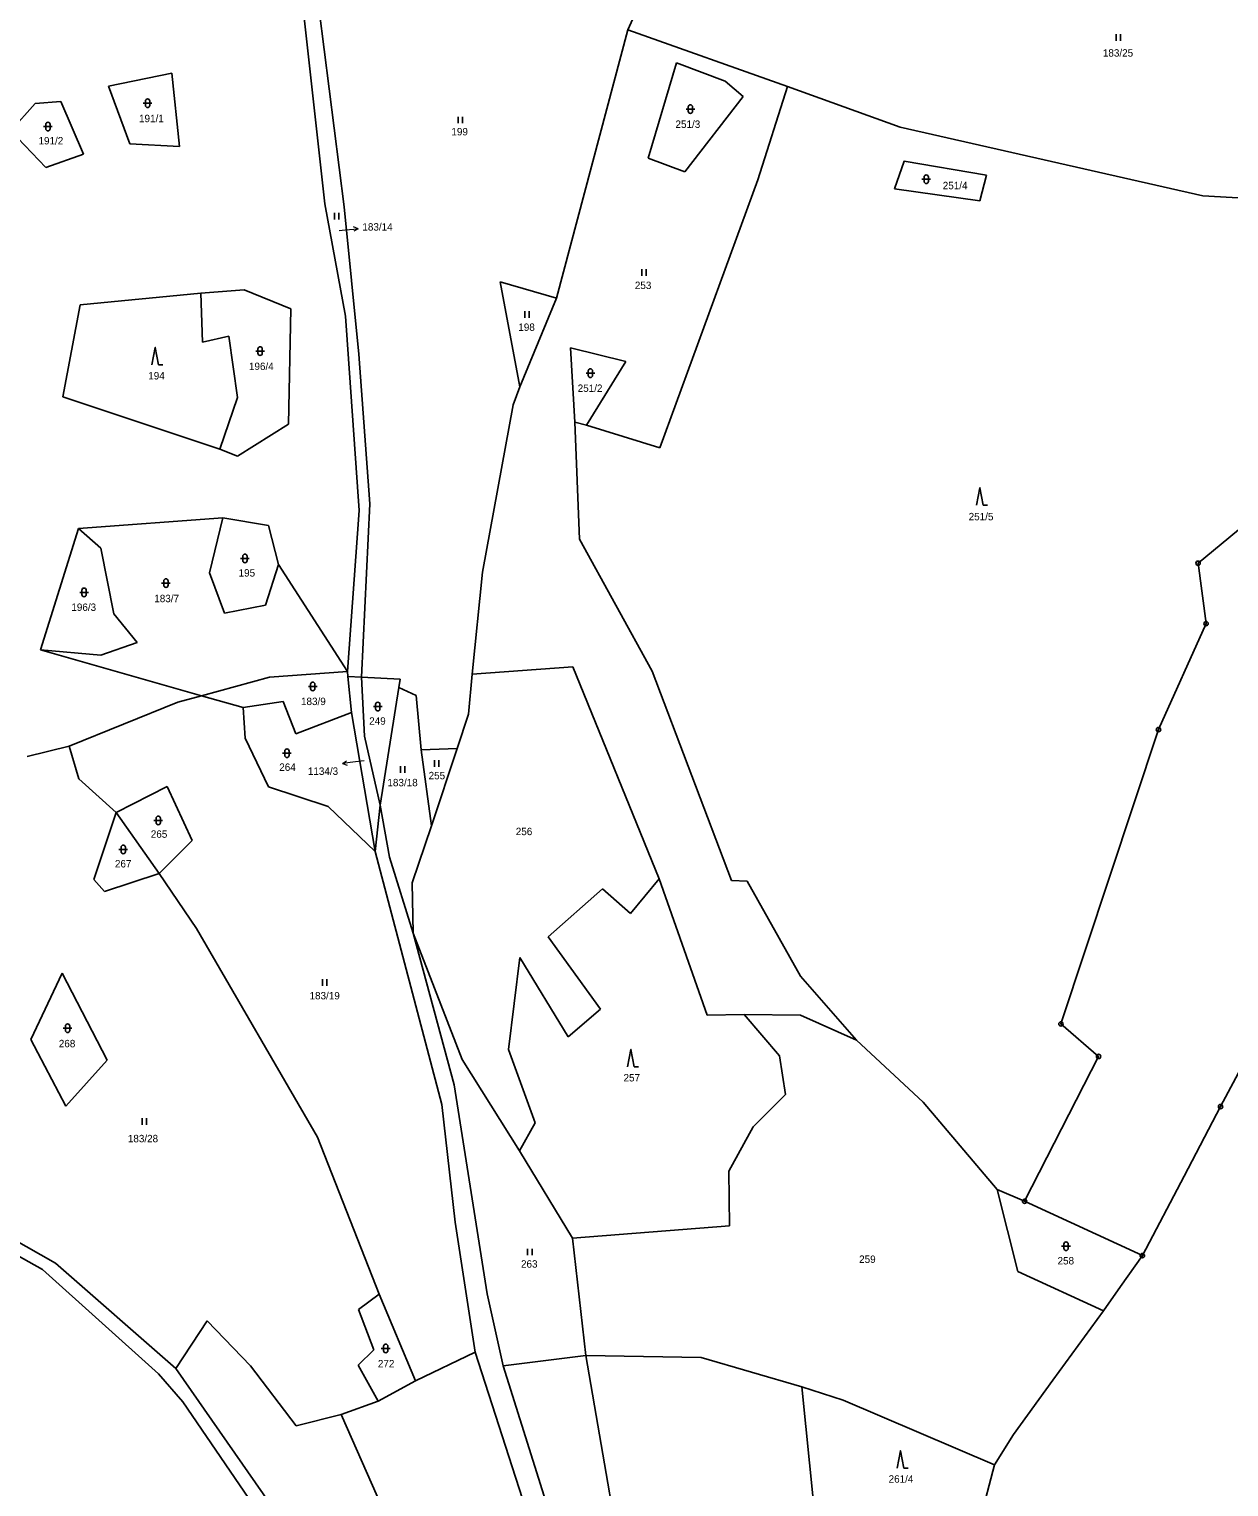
# Model space of a CAD drawing. Extents: x -765428 to -762163, y -1107632 to -1104975.
# Drawn here: x -763021.2 to -762745.6, y -1106469 to -1106134.4 of the extents above; entities that cross this region are included whole.
import ezdxf
from ezdxf.enums import TextEntityAlignment as Align

# ---------------------------------------------------------------- set-up
doc = ezdxf.new("R2010")
doc.units = 0
doc.header["$LTSCALE"] = 0.68
for name, color, linetype, lineweight in [('1', 7, 'Continuous', 25), ('3', 7, 'Continuous', 25), ('7', 7, 'Continuous', 13), ('8', 7, 'Continuous', 25)]:
    doc.layers.add(name, color=color, linetype=linetype, lineweight=lineweight)
doc.layers.add('2', color=7, linetype='Continuous')

msp = doc.modelspace()

# ---------------------------------------------------------------- linework, layer by layer
at = {"layer": '1'}
for p, q in [((-762874.94, -1106114.98), (-762883.63, -1106134.57)), ((-762953.22, -1106174.49), (-762958.16, -1106130.43)), ((-762954.53, -1106130.03), (-762948.82, -1106175.16)), ((-762883.63, -1106134.57), (-762900.02, -1106196.11)), ((-762883.63, -1106134.57), (-762847.02, -1106147.59)), ((-762872.47, -1106142.09), (-762879.01, -1106164.03)), ((-762861.28, -1106146.3), (-762872.47, -1106142.09)), ((-763002.95, -1106147.5), (-762988.37, -1106144.49)), ((-762988.37, -1106144.49), (-762986.6, -1106161.29)), ((-762857.19, -1106149.85), (-762861.28, -1106146.3)), ((-763002.95, -1106147.5), (-762998.05, -1106160.73)), ((-762847.02, -1106147.59), (-762853.81, -1106169.01)), ((-762821.13, -1106156.89), (-762847.02, -1106147.59)), ((-763019.8, -1106151.45), (-763025.33, -1106157.75)), ((-763019.8, -1106151.45), (-763013.86, -1106150.98)), ((-763013.86, -1106150.98), (-763008.65, -1106163.09)), ((-762870.58, -1106167.18), (-762857.19, -1106149.85)), ((-763025.33, -1106157.75), (-763017.35, -1106166.16)), ((-762751.57, -1106172.68), (-762821.13, -1106156.89)), ((-763017.35, -1106166.16), (-763008.65, -1106163.09)), ((-762986.6, -1106161.29), (-762998.05, -1106160.73)), ((-762879.01, -1106164.03), (-762870.58, -1106167.18)), ((-762853.81, -1106169.01), (-762876.27, -1106230.52)), ((-762802.79, -1106173.83), (-762801.25, -1106167.93)), ((-762822.38, -1106171.04), (-762802.79, -1106173.83)), ((-762723.14, -1106174.24), (-762751.57, -1106172.68)), ((-762948.51, -1106200.27), (-762953.22, -1106174.49)), ((-762948.82, -1106175.16), (-762945.42, -1106209.03)), ((-762908.47, -1106216.48), (-762912.96, -1106192.37)), ((-762912.96, -1106192.37), (-762900.02, -1106196.11)), ((-763009.43, -1106197.65), (-762981.74, -1106195.01)), ((-762981.74, -1106195.01), (-762971.77, -1106194.24)), ((-762981.74, -1106195.01), (-762981.36, -1106206.21)), ((-762971.77, -1106194.24), (-762961.03, -1106198.6)), ((-762900.02, -1106196.11), (-762908.47, -1106216.48)), ((-763009.43, -1106197.65), (-763013.42, -1106218.83)), ((-762961.03, -1106198.6), (-762961.58, -1106225.06)), ((-762945.33, -1106244.86), (-762948.51, -1106200.27)), ((-762981.36, -1106206.21), (-762975.31, -1106204.86)), ((-762975.31, -1106204.86), (-762973.31, -1106218.96)), ((-762945.42, -1106209.03), (-762942.88, -1106243.36)), ((-762895.84, -1106224.64), (-762896.83, -1106207.57)), ((-762896.83, -1106207.57), (-762884.12, -1106210.68)), ((-762884.12, -1106210.68), (-762893.17, -1106225.31)), ((-762908.47, -1106216.48), (-762909.99, -1106220.62)), ((-762699.78, -1106213.38), (-762752.7, -1106256.98)), ((-763013.42, -1106218.83), (-762977.37, -1106230.81)), ((-762973.31, -1106218.96), (-762977.37, -1106230.81)), ((-762909.99, -1106220.62), (-762917.04, -1106259.06)), ((-762961.58, -1106225.06), (-762973.27, -1106232.38)), ((-762893.17, -1106225.31), (-762895.84, -1106224.64)), ((-762895.84, -1106224.64), (-762894.75, -1106251.44)), ((-762876.27, -1106230.52), (-762893.17, -1106225.31)), ((-762973.27, -1106232.38), (-762977.37, -1106230.81)), ((-762942.88, -1106243.36), (-762944.85, -1106283.11)), ((-763009.82, -1106249.02), (-762976.69, -1106246.6)), ((-762976.69, -1106246.6), (-762979.73, -1106259.18)), ((-762976.69, -1106246.6), (-762966.19, -1106248.32)), ((-762945.33, -1106244.86), (-762948.06, -1106281.83)), ((-763018.57, -1106276.87), (-763009.82, -1106249.02)), ((-763009.82, -1106249.02), (-763004.68, -1106253.55)), ((-762966.19, -1106248.32), (-762963.92, -1106257.26)), ((-762894.75, -1106251.44), (-762878.05, -1106281.74)), ((-763004.68, -1106253.55), (-763001.73, -1106268.63)), ((-762976.25, -1106268.47), (-762979.73, -1106259.18)), ((-762963.92, -1106257.26), (-762966.86, -1106266.59)), ((-762948.06, -1106281.83), (-762963.92, -1106257.26)), ((-762917.04, -1106259.06), (-762919.4, -1106282.45)), ((-762752.7, -1106256.98), (-762750.86, -1106270.85)), ((-762966.86, -1106266.59), (-762976.25, -1106268.47)), ((-763001.73, -1106268.63), (-762996.33, -1106275.2)), ((-762750.86, -1106270.85), (-762761.78, -1106295.18)), ((-763018.57, -1106276.87), (-762981.56, -1106287.41)), ((-763004.69, -1106278.08), (-763018.57, -1106276.87)), ((-762996.33, -1106275.2), (-763004.69, -1106278.08)), ((-762965.93, -1106283.17), (-762981.56, -1106287.41)), ((-762948.06, -1106281.83), (-762965.93, -1106283.17)), ((-762947.94, -1106282.96), (-762948.06, -1106281.83)), ((-762947.09, -1106291.24), (-762947.94, -1106282.96)), ((-762944.85, -1106283.11), (-762947.94, -1106282.96)), ((-762944.85, -1106283.11), (-762935.91, -1106283.6)), ((-762944.17, -1106296.72), (-762944.85, -1106283.11)), ((-762935.91, -1106283.6), (-762936.22, -1106285.53)), ((-762919.4, -1106282.45), (-762920.27, -1106291.64)), ((-762896.27, -1106280.77), (-762919.4, -1106282.45)), ((-762876.47, -1106329.44), (-762896.27, -1106280.77)), ((-762878.05, -1106281.74), (-762859.84, -1106329.79)), ((-762936.22, -1106285.53), (-762940.52, -1106312.56)), ((-762932.27, -1106287.34), (-762936.22, -1106285.53)), ((-762986.97, -1106288.88), (-763011.94, -1106299.02)), ((-762981.56, -1106287.41), (-762986.97, -1106288.88)), ((-762981.56, -1106287.41), (-762972.02, -1106290.13)), ((-762972.02, -1106290.13), (-762962.81, -1106288.74)), ((-762971.56, -1106297.12), (-762972.02, -1106290.13)), ((-762962.81, -1106288.74), (-762959.91, -1106296.19)), ((-762931.15, -1106299.82), (-762932.27, -1106287.34)), ((-762959.91, -1106296.19), (-762947.09, -1106291.24)), ((-762947.09, -1106291.24), (-762941.72, -1106323.15)), ((-762920.27, -1106291.64), (-762922.88, -1106299.54)), ((-762940.52, -1106312.56), (-762944.17, -1106296.72)), ((-762761.78, -1106295.18), (-762784.18, -1106362.74)), ((-763021.57, -1106301.33), (-763011.94, -1106299.02)), ((-763011.94, -1106299.02), (-763009.74, -1106306.46)), ((-762966.18, -1106308.31), (-762971.56, -1106297.12)), ((-762931.15, -1106299.82), (-762922.88, -1106299.54)), ((-762928.73, -1106317.26), (-762931.15, -1106299.82)), ((-762922.88, -1106299.54), (-762928.73, -1106317.26)), ((-763009.74, -1106306.46), (-763001.15, -1106314.19)), ((-763001.15, -1106314.19), (-762989.48, -1106308.21)), ((-762989.48, -1106308.21), (-762983.75, -1106320.67)), ((-762952.46, -1106312.86), (-762966.18, -1106308.31)), ((-762941.72, -1106323.15), (-762952.46, -1106312.86)), ((-762941.72, -1106323.15), (-762940.52, -1106312.56)), ((-762940.52, -1106312.56), (-762938.4, -1106324.46)), ((-763001.15, -1106314.19), (-763006.26, -1106329.57)), ((-763001.15, -1106314.19), (-762991.29, -1106328.18)), ((-762928.73, -1106317.26), (-762933.18, -1106330.37)), ((-762991.29, -1106328.18), (-762983.75, -1106320.67)), ((-762941.72, -1106323.15), (-762926.38, -1106381.22)), ((-762938.4, -1106324.46), (-762932.94, -1106341.9)), ((-763003.81, -1106332.37), (-763006.26, -1106329.57)), ((-762991.29, -1106328.18), (-763003.81, -1106332.37)), ((-762982.74, -1106340.81), (-762991.29, -1106328.18)), ((-762933.18, -1106330.37), (-762932.94, -1106341.9)), ((-762883.03, -1106337.38), (-762876.47, -1106329.44)), ((-762865.46, -1106360.74), (-762876.47, -1106329.44)), ((-762859.84, -1106329.79), (-762856.21, -1106329.95)), ((-762856.21, -1106329.95), (-762844.02, -1106351.77)), ((-762901.92, -1106342.78), (-762889.48, -1106331.73)), ((-762889.48, -1106331.73), (-762883.03, -1106337.38)), ((-762954.96, -1106388.71), (-762982.74, -1106340.81)), ((-762932.94, -1106341.9), (-762921.73, -1106370.95)), ((-762932.94, -1106341.9), (-762923.54, -1106376.71)), ((-762889.91, -1106359.38), (-762901.92, -1106342.78)), ((-762911.04, -1106368.65), (-762908.47, -1106347.47)), ((-762908.47, -1106347.47), (-762897.32, -1106365.68)), ((-762747.53, -1106381.72), (-762729.6, -1106347.98)), ((-763020.74, -1106366.32), (-763013.55, -1106351.06)), ((-763013.55, -1106351.06), (-763003.25, -1106371.1)), ((-762844.02, -1106351.77), (-762831.17, -1106366.51)), ((-762897.32, -1106365.68), (-762889.91, -1106359.38)), ((-762856.93, -1106360.55), (-762865.46, -1106360.74)), ((-762848.84, -1106370.1), (-762856.93, -1106360.55)), ((-762844.02, -1106360.74), (-762856.93, -1106360.55)), ((-762831.17, -1106366.51), (-762844.02, -1106360.74)), ((-762784.18, -1106362.74), (-762775.53, -1106370.22)), ((-763012.76, -1106381.62), (-763020.74, -1106366.32)), ((-762831.17, -1106366.51), (-762815.82, -1106380.71)), ((-762904.96, -1106385.42), (-762911.04, -1106368.65)), ((-762847.43, -1106378.98), (-762848.84, -1106370.1)), ((-762775.53, -1106370.22), (-762792.54, -1106403.46)), ((-763003.25, -1106371.1), (-763012.76, -1106381.62)), ((-762921.73, -1106370.95), (-762908.57, -1106391.9)), ((-762923.54, -1106376.71), (-762915.96, -1106424.68)), ((-762854.86, -1106386.36), (-762847.43, -1106378.98)), ((-762926.38, -1106381.22), (-762923.34, -1106408.29)), ((-762815.82, -1106380.71), (-762798.86, -1106400.73)), ((-762755.92, -1106397.69), (-762747.53, -1106381.72)), ((-762908.57, -1106391.9), (-762904.96, -1106385.42)), ((-762860.49, -1106396.51), (-762854.86, -1106386.36)), ((-762940.76, -1106424.75), (-762954.96, -1106388.71)), ((-762908.57, -1106391.9), (-762896.34, -1106411.96)), ((-763015.12, -1106417.7), (-763052.02, -1106396.62)), ((-762860.28, -1106409.12), (-762860.49, -1106396.51)), ((-762798.86, -1106400.73), (-762794.11, -1106419.56)), ((-762798.86, -1106400.73), (-762792.54, -1106403.46)), ((-762765.49, -1106415.92), (-762755.92, -1106397.69)), ((-762792.54, -1106403.46), (-762765.49, -1106415.92)), ((-762923.34, -1106408.29), (-762918.73, -1106438.09)), ((-762896.34, -1106411.96), (-762860.28, -1106409.12)), ((-762896.34, -1106411.96), (-762893.32, -1106438.88)), ((-762770.5, -1106423.04), (-762765.49, -1106415.92)), ((-762991.47, -1106443.04), (-763018.11, -1106419.15)), ((-762987.49, -1106441.88), (-763015.12, -1106417.7)), ((-762794.11, -1106419.56), (-762774.42, -1106428.6)), ((-762774.42, -1106428.6), (-762770.5, -1106423.04)), ((-762945.53, -1106428.28), (-762940.76, -1106424.75)), ((-762940.76, -1106424.75), (-762932.41, -1106444.7)), ((-762915.96, -1106424.68), (-762912.26, -1106441.21)), ((-762942, -1106437.59), (-762945.53, -1106428.28)), ((-762786.01, -1106444.52), (-762774.42, -1106428.6)), ((-762980.28, -1106430.9), (-762987.49, -1106441.88)), ((-762970.31, -1106441.23), (-762980.28, -1106430.9)), ((-762945.56, -1106441.12), (-762942, -1106437.59)), ((-762918.73, -1106438.09), (-762932.41, -1106444.7)), ((-762901.42, -1106491.68), (-762918.73, -1106438.09)), ((-762893.32, -1106438.88), (-762866.78, -1106439.33)), ((-762866.78, -1106439.33), (-762843.73, -1106446.08)), ((-762985.88, -1106449.49), (-762991.47, -1106443.04)), ((-762965.65, -1106473.11), (-762987.49, -1106441.88)), ((-762959.79, -1106454.99), (-762970.31, -1106441.23)), ((-762941.01, -1106449.31), (-762945.56, -1106441.12)), ((-762895.88, -1106493.35), (-762912.26, -1106441.21)), ((-762932.41, -1106444.7), (-762941.01, -1106449.31)), ((-762843.73, -1106446.08), (-762834.22, -1106449.12)), ((-762795.08, -1106456.99), (-762786.01, -1106444.52)), ((-762966.88, -1106477.27), (-762985.88, -1106449.49)), ((-762941.01, -1106449.31), (-762949.49, -1106452.43)), ((-762834.22, -1106449.12), (-762799.44, -1106463.99)), ((-762949.49, -1106452.43), (-762959.79, -1106454.99)), ((-762949.49, -1106452.43), (-762929.72, -1106497.11)), ((-762795.08, -1106456.99), (-762799.44, -1106463.99)), ((-762799.44, -1106463.99), (-762802.98, -1106477.27))]:
    msp.add_line(p, q, dxfattribs=at)
for points in [[(-762801.25, -1106167.93), (-762820.2, -1106164.7), (-762822.38, -1106171.04)], [(-763018.11, -1106419.15), (-763078.33, -1106385.39), (-763074.11, -1106444.61)], [(-762882.36, -1106502.35), (-762893.32, -1106438.88), (-762912.26, -1106441.21)], [(-762843.73, -1106446.08), (-762841.01, -1106472.61), (-762850.9, -1106471.38)]]:
    msp.add_lwpolyline(points, dxfattribs=at)
at = {"layer": '3'}
for p, q in [((-762771.521, -1106137.04), (-762771.521, -1106135.54)), ((-762770.52, -1106137.04), (-762770.52, -1106135.54)), ((-762994.961, -1106151.391), (-762992.959, -1106151.391)), ((-762994.461, -1106150.891), (-762994.461, -1106151.892)), ((-762993.459, -1106151.892), (-762993.459, -1106150.891)), ((-762870.281, -1106152.751), (-762868.279, -1106152.751)), ((-762869.781, -1106152.251), (-762869.781, -1106153.252)), ((-762868.779, -1106153.252), (-762868.779, -1106152.251)), ((-763017.331, -1106156.261), (-763017.331, -1106157.262)), ((-763016.329, -1106157.262), (-763016.329, -1106156.261)), ((-762922.621, -1106155.99), (-762922.621, -1106154.49)), ((-762921.62, -1106155.99), (-762921.62, -1106154.49)), ((-763017.831, -1106156.761), (-763015.829, -1106156.761)), ((-762816.111, -1106168.831), (-762814.109, -1106168.831)), ((-762815.611, -1106168.331), (-762815.611, -1106169.332)), ((-762814.609, -1106169.332), (-762814.609, -1106168.331)), ((-762951.021, -1106178.06), (-762951.021, -1106176.56)), ((-762950.02, -1106178.06), (-762950.02, -1106176.56)), ((-762880.411, -1106191.01), (-762880.411, -1106189.51)), ((-762879.41, -1106191.01), (-762879.41, -1106189.51)), ((-762907.301, -1106200.64), (-762907.301, -1106199.14)), ((-762906.3, -1106200.64), (-762906.3, -1106199.14)), ((-762969.101, -1106208.301), (-762967.099, -1106208.301)), ((-762968.601, -1106207.801), (-762968.601, -1106208.802)), ((-762967.599, -1106208.802), (-762967.599, -1106207.801)), ((-762991.45, -1106211.44), (-762990.454, -1106211.44)), ((-762893.261, -1106213.361), (-762891.259, -1106213.361)), ((-762892.761, -1106212.861), (-762892.761, -1106213.862)), ((-762891.759, -1106213.862), (-762891.759, -1106212.861)), ((-762802.04, -1106243.67), (-762801.044, -1106243.67)), ((-762972.601, -1106255.901), (-762970.599, -1106255.901)), ((-762972.101, -1106255.401), (-762972.101, -1106256.402)), ((-762971.099, -1106256.402), (-762971.099, -1106255.401)), ((-763009.041, -1106263.181), (-763009.041, -1106264.182)), ((-763008.039, -1106264.182), (-763008.039, -1106263.181)), ((-762990.731, -1106261.561), (-762988.729, -1106261.561)), ((-762990.231, -1106261.061), (-762990.231, -1106262.062)), ((-762989.229, -1106262.062), (-762989.229, -1106261.061)), ((-763009.541, -1106263.681), (-763007.539, -1106263.681)), ((-762957.021, -1106285.281), (-762955.019, -1106285.281)), ((-762956.521, -1106284.781), (-762956.521, -1106285.782)), ((-762955.519, -1106285.782), (-762955.519, -1106284.781)), ((-762942.081, -1106289.891), (-762940.079, -1106289.891)), ((-762941.581, -1106289.391), (-762941.581, -1106290.392)), ((-762940.579, -1106290.392), (-762940.579, -1106289.391)), ((-762962.451, -1106300.111), (-762962.451, -1106301.112)), ((-762961.449, -1106301.112), (-762961.449, -1106300.111)), ((-762962.951, -1106300.611), (-762960.949, -1106300.611)), ((-762935.901, -1106305.07), (-762935.901, -1106303.57)), ((-762934.9, -1106305.07), (-762934.9, -1106303.57)), ((-762928.081, -1106303.72), (-762928.081, -1106302.22)), ((-762927.08, -1106303.72), (-762927.08, -1106302.22)), ((-762992.511, -1106316.041), (-762990.509, -1106316.041)), ((-762992.011, -1106315.541), (-762992.011, -1106316.542)), ((-762991.009, -1106316.542), (-762991.009, -1106315.541)), ((-763000.551, -1106322.691), (-762998.549, -1106322.691)), ((-763000.051, -1106322.191), (-763000.051, -1106323.192)), ((-762999.049, -1106323.192), (-762999.049, -1106322.191)), ((-762953.791, -1106353.99), (-762953.791, -1106352.49)), ((-762952.79, -1106353.99), (-762952.79, -1106352.49)), ((-763013.321, -1106363.731), (-763011.319, -1106363.731)), ((-763012.821, -1106363.231), (-763012.821, -1106364.232)), ((-763011.819, -1106364.232), (-763011.819, -1106363.231)), ((-762882.2, -1106372.59), (-762881.204, -1106372.59)), ((-762995.191, -1106385.89), (-762995.191, -1106384.39)), ((-762994.19, -1106385.89), (-762994.19, -1106384.39)), ((-762784.021, -1106413.781), (-762782.019, -1106413.781)), ((-762783.521, -1106413.281), (-762783.521, -1106414.282)), ((-762782.519, -1106414.282), (-762782.519, -1106413.281)), ((-762906.661, -1106415.86), (-762906.661, -1106414.36)), ((-762905.66, -1106415.86), (-762905.66, -1106414.36)), ((-762940.271, -1106437.251), (-762938.269, -1106437.251)), ((-762939.771, -1106436.751), (-762939.771, -1106437.752)), ((-762938.769, -1106437.752), (-762938.769, -1106436.751)), ((-762820.3, -1106464.72), (-762819.304, -1106464.72))]:
    msp.add_line(p, q, dxfattribs=at)
for points in [[(-762991.45, -1106211.44), (-762992.2, -1106207.44), (-762992.95, -1106211.44)], [(-762802.04, -1106243.67), (-762802.79, -1106239.67), (-762803.54, -1106243.67)], [(-762882.2, -1106372.59), (-762882.95, -1106368.59), (-762883.7, -1106372.59)], [(-762820.3, -1106464.72), (-762821.05, -1106460.72), (-762821.8, -1106464.72)]]:
    msp.add_lwpolyline(points, dxfattribs=at)
for centre, start, end in [((-762993.96, -1106150.8909), 0, 180), ((-762993.96, -1106151.8909), 180, 359.98789), ((-762869.28, -1106152.2509), 0, 180), ((-763016.83, -1106156.2609), 0, 180), ((-762869.28, -1106153.2509), 180, 359.98789), ((-763016.83, -1106157.2609), 180, 359.98789), ((-762815.11, -1106168.3309), 0, 180), ((-762815.11, -1106169.3309), 180, 359.98789), ((-762968.1, -1106207.8009), 0, 180), ((-762968.1, -1106208.8009), 180, 359.98789), ((-762892.26, -1106212.8609), 0, 180), ((-762892.26, -1106213.8609), 180, 359.98789), ((-762971.6, -1106255.4009), 0, 180), ((-762971.6, -1106256.4009), 180, 359.98789), ((-763008.54, -1106263.1809), 0, 180), ((-762989.73, -1106261.0609), 0, 180), ((-762989.73, -1106262.0609), 180, 359.98789), ((-763008.54, -1106264.1809), 180, 359.98789), ((-762956.02, -1106284.7809), 0, 180), ((-762956.02, -1106285.7809), 180, 359.98789), ((-762941.08, -1106289.3909), 0, 180), ((-762941.08, -1106290.3909), 180, 359.98789), ((-762961.95, -1106300.1109), 0, 180), ((-762961.95, -1106301.1109), 180, 359.98789), ((-762991.51, -1106315.5409), 0, 180), ((-762991.51, -1106316.5409), 180, 359.98789), ((-762999.55, -1106322.1909), 0, 180), ((-762999.55, -1106323.1909), 180, 359.98789), ((-763012.32, -1106363.2309), 0, 180), ((-763012.32, -1106364.2309), 180, 359.98789), ((-762783.02, -1106413.2809), 0, 180), ((-762783.02, -1106414.2809), 180, 359.98789), ((-762939.27, -1106436.7509), 0, 180), ((-762939.27, -1106437.7509), 180, 359.98789)]:
    msp.add_arc(centre, 0.5, start, end, dxfattribs=at)
at = {"layer": '7'}
for p, q in [((-762945.62, -1106180.208), (-762946.662, -1106179.797)), ((-762949.199, -1106302.986), (-762948.144, -1106303.361))]:
    msp.add_line(p, q, dxfattribs=at)
for points in [[(-762949.97, -1106180.59), (-762948.61, -1106180.47), (-762945.62, -1106180.208), (-762946.574, -1106180.795)], [(-762944.19, -1106302.36), (-762946.22, -1106302.62), (-762949.199, -1106302.986), (-762948.266, -1106302.367)]]:
    msp.add_lwpolyline(points, dxfattribs=at)
at = {"layer": '8'}
for centre, radius in [((-762752.7, -1106256.9799), 0.5), ((-762752.7, -1106256.9799), 0.0303), ((-762750.86, -1106270.8499), 0.5), ((-762750.86, -1106270.8499), 0.0303), ((-762761.78, -1106295.1799), 0.5), ((-762761.78, -1106295.1799), 0.0303), ((-762784.18, -1106362.7399), 0.5), ((-762784.18, -1106362.7399), 0.0303), ((-762775.53, -1106370.2199), 0.5), ((-762775.53, -1106370.2199), 0.0303), ((-762747.53, -1106381.7199), 0.5), ((-762747.53, -1106381.7199), 0.0303), ((-762792.54, -1106403.4599), 0.5), ((-762792.54, -1106403.4599), 0.0303), ((-762765.49, -1106415.9199), 0.5), ((-762765.49, -1106415.9199), 0.0303)]:
    msp.add_circle(centre, radius, dxfattribs=at)

# ---------------------------------------------------------------- texts
at = {"layer": '2'}
for s, p in [('183/25', (-762771.08, -1106140.695)), ('199', (-762922.279, -1106158.775)), ('253', (-762880.149, -1106194.045)), ('198', (-762906.909, -1106203.655)), ('183/7', (-762989.57, -1106265.935)), ('183/9', (-762955.87, -1106289.555)), ('183/18', (-762935.39, -1106308.195)), ('183/19', (-762953.28, -1106357.115)), ('183/28', (-762995.01, -1106389.915))]:
    msp.add_text(s, height=1.7, dxfattribs=at).set_placement(p, align=Align.CENTER)
for s, p in [('191/1', (-762995.92, -1106155.745)), ('251/3', (-762872.71, -1106157.055)), ('191/2', (-763019.01, -1106160.855)), ('251/4', (-762811.33, -1106171.135)), ('183/14', (-762944.62, -1106180.635)), ('194', (-762993.8, -1106214.805)), ('196/4', (-762970.67, -1106212.645)), ('251/2', (-762895.17, -1106217.665)), ('251/5', (-762805.38, -1106247.135)), ('195', (-762973.05, -1106260.055)), ('196/3', (-763011.46, -1106267.935)), ('249', (-762943.06, -1106294.065)), ('264', (-762963.71, -1106304.655)), ('255', (-762929.41, -1106306.585)), ('265', (-762993.21, -1106320.015)), ('256', (-762909.39, -1106319.415)), ('267', (-763001.45, -1106326.825)), ('268', (-763014.34, -1106368.105)), ('257', (-762884.64, -1106375.955)), ('263', (-762908.19, -1106418.695)), ('259', (-762830.53, -1106417.605)), ('258', (-762784.96, -1106417.965)), ('272', (-762941.06, -1106441.585)), ('261/4', (-762823.76, -1106468.055))]:
    msp.add_text(s, height=1.7, dxfattribs=at).set_placement(p)
msp.add_text('1134/3', height=1.7, dxfattribs=at).set_placement((-762950.189, -1106305.575), align=Align.RIGHT)

doc.saveas('drawing.dxf')
